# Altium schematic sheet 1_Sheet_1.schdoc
size 1005 x 452 mm; Name: A_A2; Symbol: A_A2; Device: A_A2; @Project Name: SpEIT_RHIZOTRON_TESTBOARD; REV: 1.0; Date: 2023-06-16; Sheet: 1/1; Draw By: ENOW MAGKEN; Company: UNIVERSITY OF MANCHESTER; Convert to PCB: yes; Add into BOM: yes
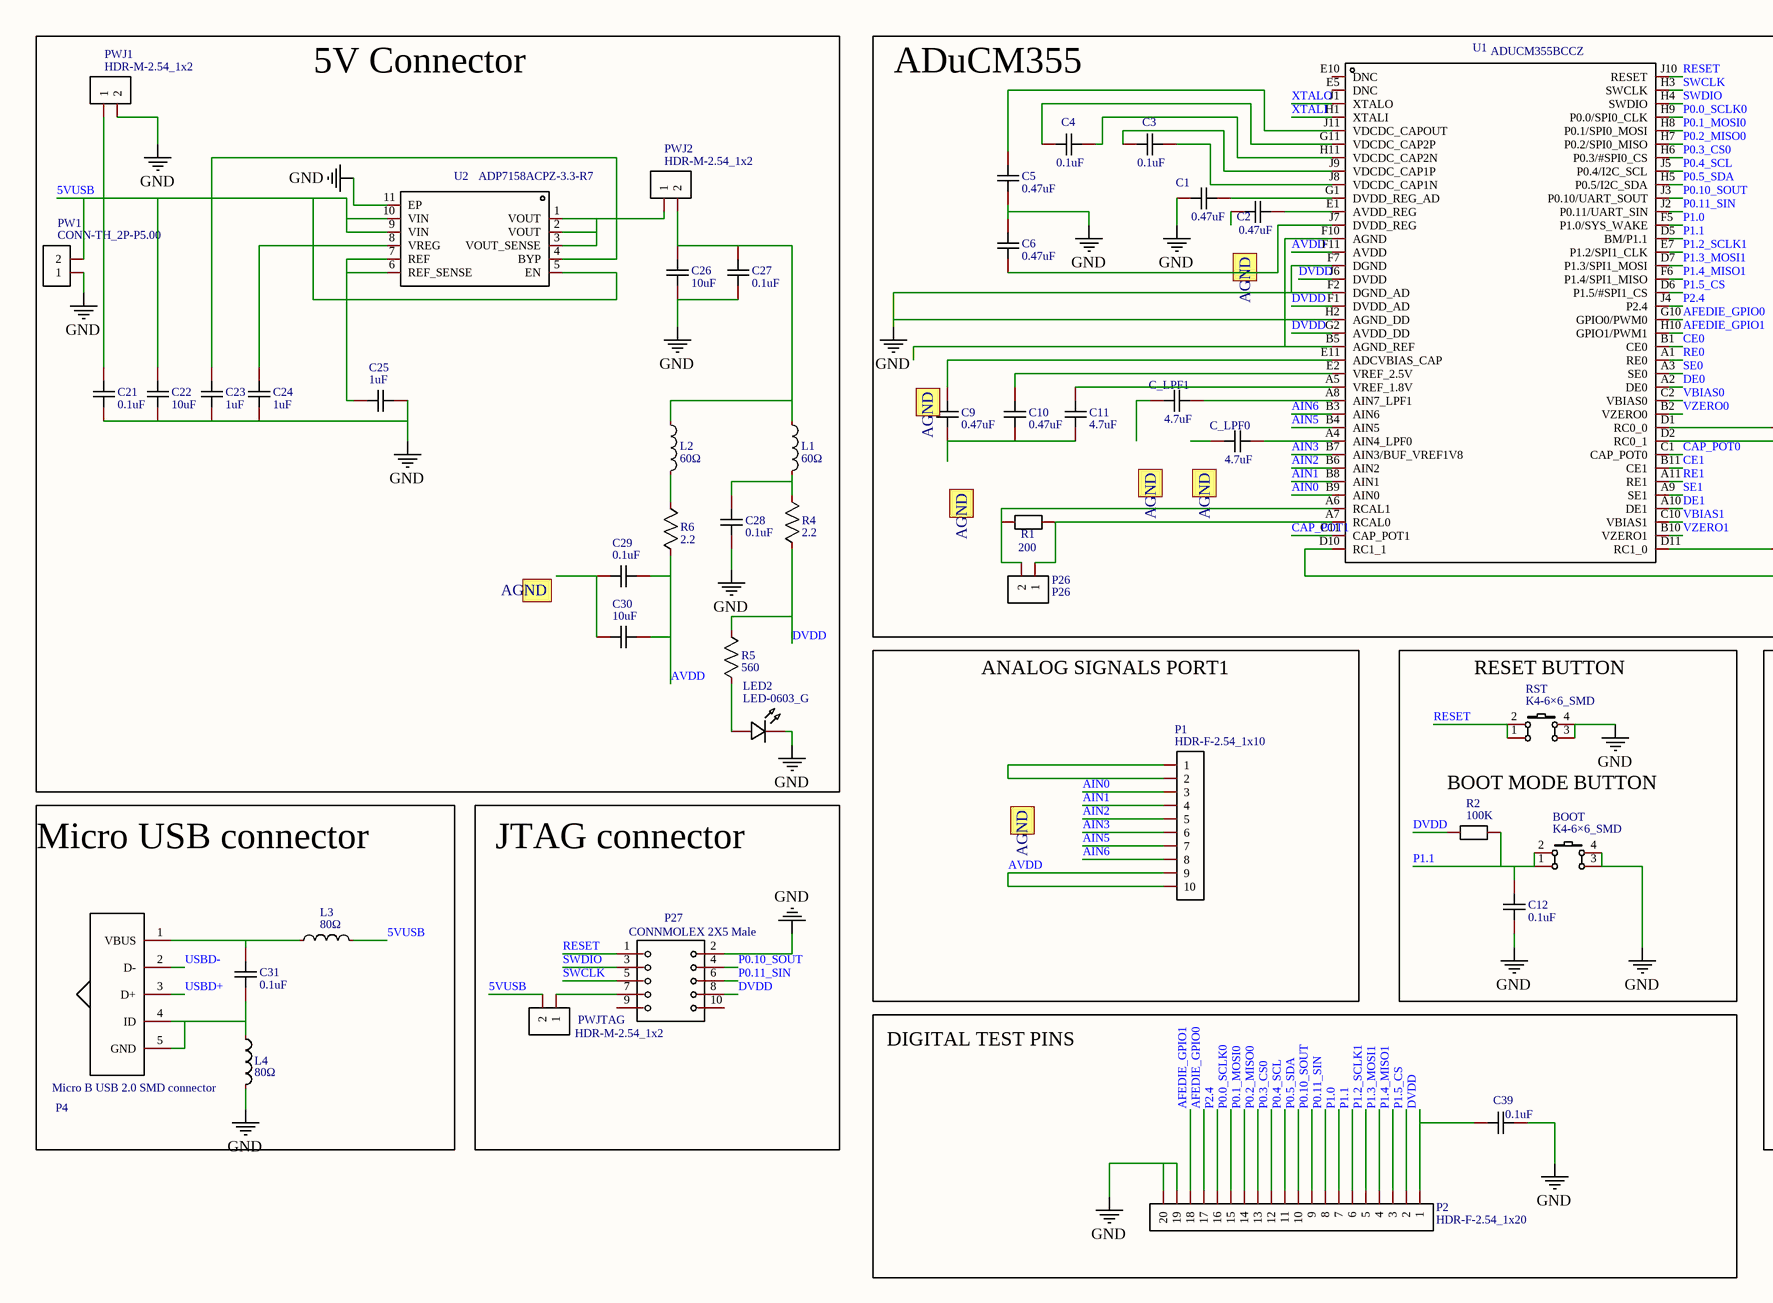
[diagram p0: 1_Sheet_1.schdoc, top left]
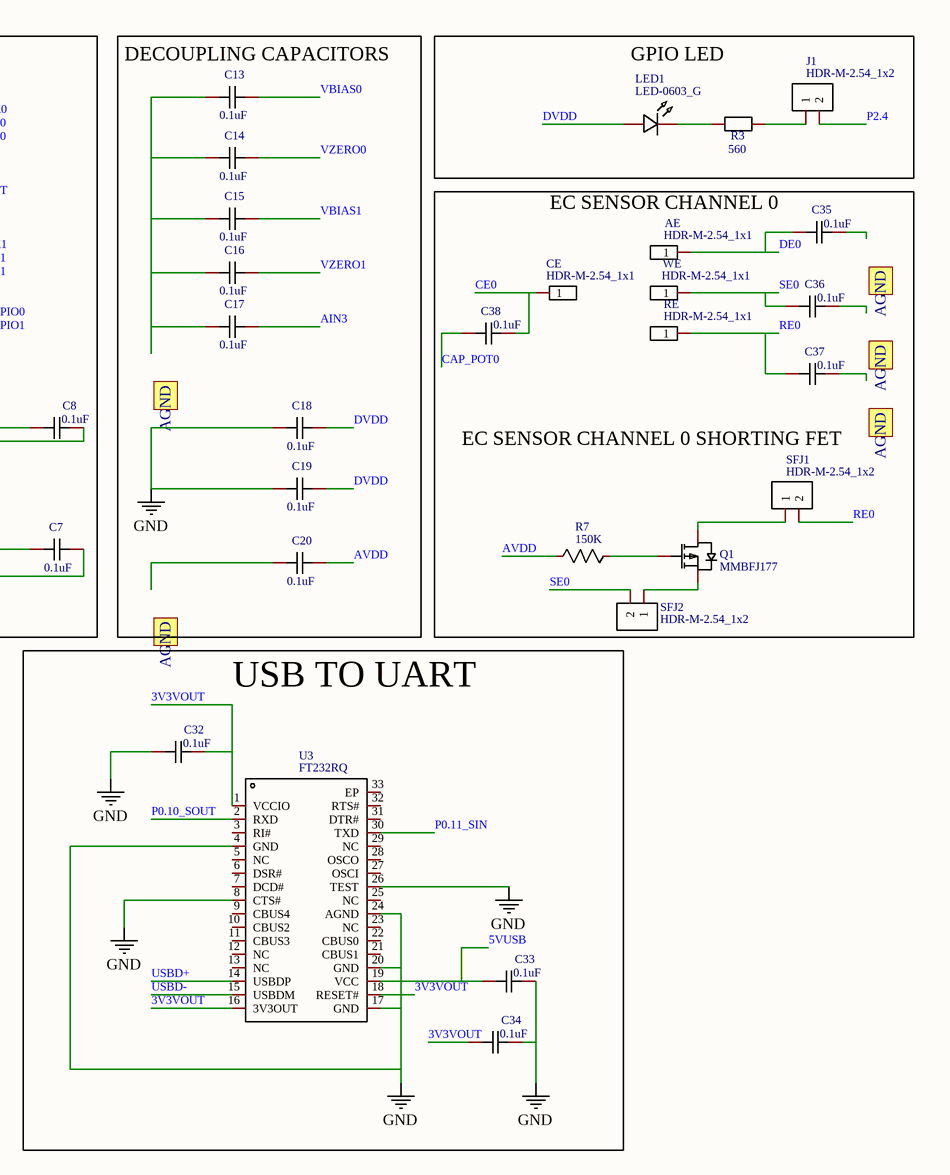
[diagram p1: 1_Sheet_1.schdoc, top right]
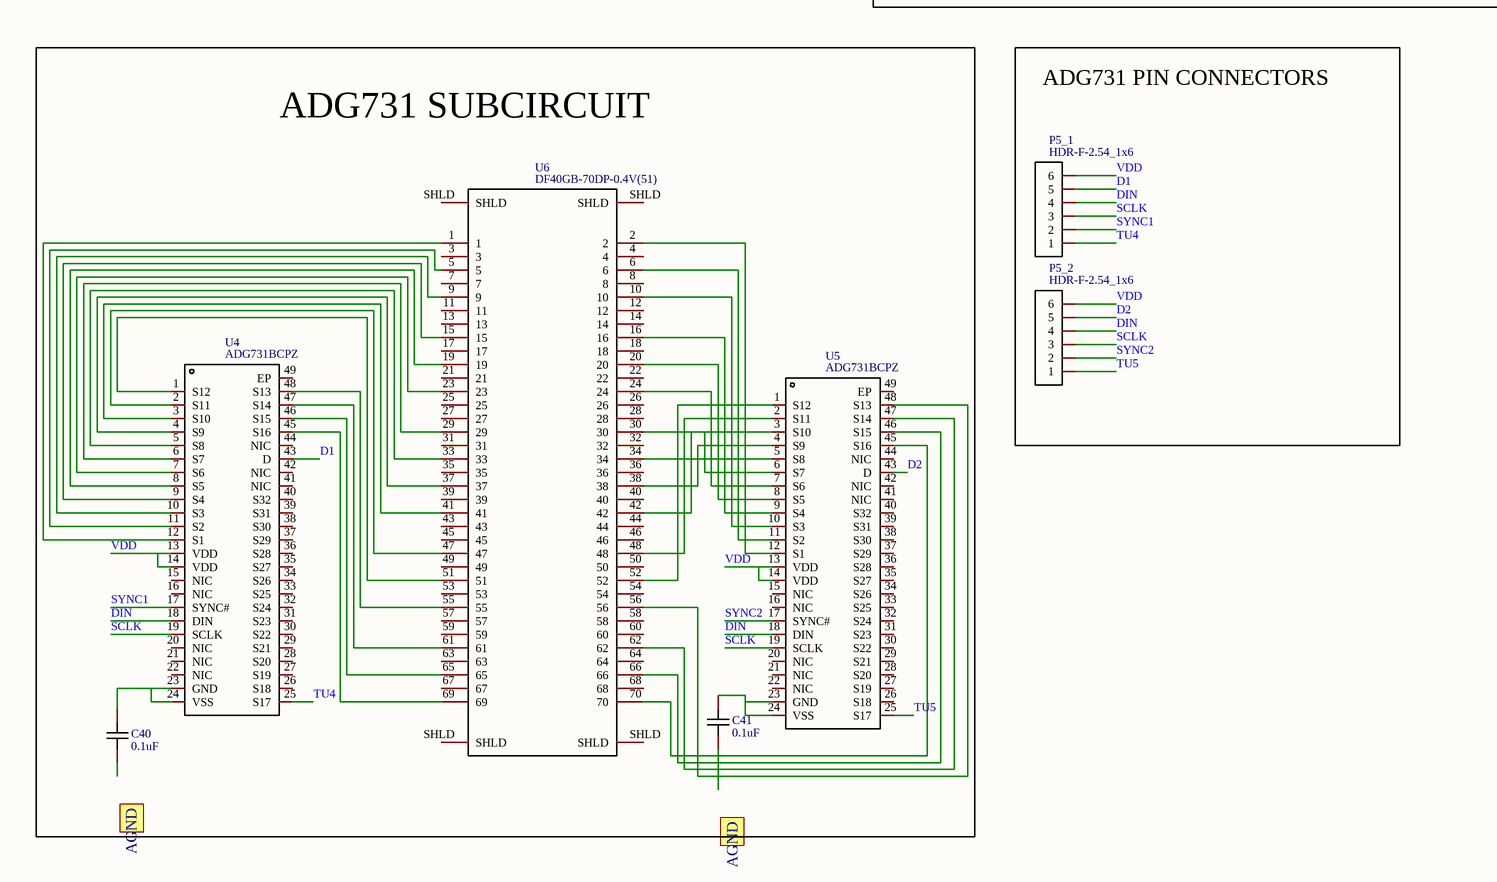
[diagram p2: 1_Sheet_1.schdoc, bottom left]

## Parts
AE  HDR-M-2.54_1x1  [HDR-M-2.54_1X1]
BOOT  K4-6×6_SMD  [KEY-SMD_4P-L6.0-W6.0-P3.90-LS10.0]
C1  0.47uF  [C0603]
C2  0.47uF  [C0603]
C3  0.1uF  [C0603]
C4  0.1uF  [C0603]
C5  0.47uF  [C0603]
C6  0.47uF  [C0603]
C7  0.1uF  [C0603]
C8  0.1uF  [C0603]
C9  0.47uF  [C0603]
C10  0.47uF  [C0603]
C11  4.7uF  [C0603]
C12  0.1uF  [C0603]
C13  0.1uF  [C0603]
C14  0.1uF  [C0603]
C15  0.1uF  [C0603]
C16  0.1uF  [C0603]
C17  0.1uF  [C0603]
C18  0.1uF  [C0603]
C19  0.1uF  [C0603]
C20  0.1uF  [C0603]
C21  0.1uF  [C0603]
C22  10uF  [C0603]
C23  1uF  [C0603]
C24  1uF  [C0603]
C25  1uF  [C0603]
C26  10uF  [C0603]
C27  0.1uF  [C0603]
C28  0.1uF  [C0603]
C29  0.1uF  [C0603]
C30  10uF  [C0603]
C31  0.1uF  [C0603]
C32  0.1uF  [C0603]
C33  0.1uF  [C0603]
C34  0.1uF  [C0603]
C35  0.1uF  [C0603]
C36  0.1uF  [C0603]
C37  0.1uF  [C0603]
C38  0.1uF  [C0603]
C39  0.1uF  [C0603]
C40  0.1uF  [C0603]
C41  0.1uF  [C0603]
C_LPF0  4.7uF  [C0603]
C_LPF1  4.7uF  [C0603]
CE  HDR-M-2.54_1x1  [HDR-M-2.54_1X1]
J1  HDR-M-2.54_1x2  [HDR-M-2.54_1X2]
L1  60Ω  [L0603]
L2  60Ω  [L0603]
L3  80Ω  [L1806]
L4  80Ω  [L1806]
LED1  LED-0603_G  [LED0603_GREEN]
LED2  LED-0603_G  [LED0603_GREEN]
P1  HDR-F-2.54_1x10  [HDR-F-2.54_1X10]
P2  HDR-F-2.54_1x20  [HDR-F-2.54_1X20]
P4  Micro B USB 2.0 SMD connector  [SD-47346-001]
P5_1  HDR-F-2.54_1x6  [HDR-F-2.54_1X6]
P5_2  HDR-F-2.54_1x6  [HDR-F-2.54_1X6]
P26  P26  [HDR-F-2.54_1X2]
P27  CONNMOLEX 2X5 Male  [JTAG-10PIN-2.54MM-PTH]
PW1  CONN-TH_2P-P5.00  [CONN-TH_2P-P5.00]
PWJ1  HDR-M-2.54_1x2  [HDR-M-2.54_1X2]
PWJ2  HDR-M-2.54_1x2  [HDR-M-2.54_1X2]
PWJTAG  HDR-M-2.54_1x2  [HDR-M-2.54_1X2]
Q1  MMBFJ177  [SOT-23-3_L3.0-W1.7-P0.95-LS2.9-BR]
R1  200  [R0603]
R2  100K  [R0603]
R3  560  [R0603]
R4  2.2  [R0603]
R5  560  [R0603]
R6  2.2  [R0603]
R7  150K  [R0603]
RE  HDR-M-2.54_1x1  [HDR-M-2.54_1X1]
RST  K4-6×6_SMD  [KEY-SMD_4P-L6.0-W6.0-P3.90-LS10.0]
SFJ1  HDR-M-2.54_1x2  [HDR-M-2.54_1X2]
SFJ2  HDR-M-2.54_1x2  [HDR-M-2.54_1X2]
U1  ADUCM355BCCZ  [LGA-72_L6.0-W5.0-TL_ADUCM355BCCZ-RL7]
U2  ADP7158ACPZ-3.3-R7  [LFCSP-10_L3.0-W3.0-P0.50-BL-EP]
U3  FT232RQ  [QFN-32_L5.0-W5.0-P0.50-BL-EP]
U4  ADG731BCPZ  [LFCSP-48_L7.0-W7.0-P0.50-TL-EP5.1]
U5  ADG731BCPZ  [LFCSP-48_L7.0-W7.0-P0.50-TL-EP5.1]
U6  DF40GB-70DP-0.4V(51)  [HIROSE DF40GB-70DP-0.4V(51)]
WE  HDR-M-2.54_1x1  [HDR-M-2.54_1X1]

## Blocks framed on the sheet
5V Connector: C21-C30 L1 L2 LED2 PW1 PWJ1 PWJ2 R4-R6 U2
ADuCM355: C1-C11 C_LPF0 C_LPF1 P26 R1 U1
DECOUPLING CAPACITORS: C13-C20
GPIO LED: J1 LED1 R3
ANALOG SIGNALS PORT1: P1
USB TO UART: C32-C34 U3
Micro USB connector: C31 L3 L4 P4
JTAG connector: P27 PWJTAG
DIGITAL TEST PINS: C39 P2
ADG731 SUBCIRCUIT: C40 C41 U4-U6
ADG731 PIN CONNECTORS: P5_1 P5_2

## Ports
AGND (out)

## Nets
GND: BOOT.3 BOOT.4 C1.1 C5.1 C6.2 C12.1 C18.1 C19.1 C21.1 C22.1 C23.1 C24.1 C25.1 C26.1 C27.1 C28.1 C32.1 C33.2 C34.2 C39.2 L4.2 LED2.2 P2.19 P2.20 P27.2 PW1.1 PWJ1.2 RST.3 RST.4 U1.F2(DGND_AD) U1.F7(DGND) U1.H2(AGND_DD) U2.11(EP) U3.4(GND) U3.8(CTS#) U3.17(GND) U3.20(GND) U3.24(AGND) U3.26(TEST)
3V3VOUT: C32.2 C34.1 U3.1(VCCIO) U3.16(3V3OUT) U3.18(RESET#)
5VUSB: C21.2 C22.2 C33.1 L3.2 PW1.2 PWJ1.1 PWJTAG.2 U2.5(EN) U2.9(VIN) U2.10(VIN) U3.19(VCC)
AFEDIE_GPIO0: P2.17 U1.G10(GPIO0/PWM0)
AFEDIE_GPIO1: P2.18 U1.H10(GPIO1/PWM1)
AIN0: P1.3 U1.B9(AIN0)
AIN1: P1.4 U1.B8(AIN1)
AIN2: P1.5 U1.B6(AIN2)
AIN3: C17.2 P1.6 U1.B7(AIN3/BUF_VREF1V8)
AIN5: P1.7 U1.B4(AIN5)
AIN6: P1.8 U1.B3(AIN6)
AVDD: C20.2 C29.1 C30.1 P1.9 P1.10 R6.1 R7.2 U1.F11(AVDD)
CAP_POT0: C38.1 U1.C1(CAP_POT0)
CAP_POT1: U1.C11(CAP_POT1)
CE0: C38.2 CE.1 U1.B1(CE0)
CE1: U1.B11(CE1)
D1: P5_1.5 U4.43(D)
D2: P5_2.5 U5.43(D)
DE0: AE.1 C35.1 U1.A2(DE0)
DE1: U1.A10(DE1)
DIN: P5_1.4 P5_2.4 U4.18(DIN) U5.18(DIN)
DVDD: C18.2 C19.2 C39.1 LED1.1 P2.1 P27.8 R2.2 R4.1 R5.2 U1.F1(DVDD_AD) U1.G2(AVDD_DD) U1.J6(DVDD)
P0.0_SCLK0: P2.15 U1.H9(P0.0/SPI0_CLK)
P0.1_MOSI0: P2.14 U1.H8(P0.1/SPI0_MOSI)
P0.2_MISO0: P2.13 U1.H7(P0.2/SPI0_MISO)
P0.3_CS0: P2.12 U1.H6(P0.3/#SPI0_CS)
P0.4_SCL: P2.11 U1.J5(P0.4/I2C_SCL)
P0.5_SDA: P2.10 U1.H5(P0.5/I2C_SDA)
P0.10_SOUT: P2.9 P27.4 U1.J3(P0.10/UART_SOUT) U3.2(RXD)
P0.11_SIN: P2.8 P27.6 U1.J2(P0.11/UART_SIN) U3.30(TXD)
P1.0: P2.7 U1.F5(P1.0/SYS_WAKE)
P1.1: BOOT.1 BOOT.2 C12.2 P2.6 R2.1 U1.D5(BM/P1.1)
P1.2_SCLK1: P2.5 U1.E7(P1.2/SPI1_CLK)
P1.3_MOSI1: P2.4 U1.D7(P1.3/SPI1_MOSI)
P1.4_MISO1: P2.3 U1.F6(P1.4/SPI1_MISO)
P1.5_CS: P2.2 U1.D6(P1.5/#SPI1_CS)
P2.4: J1.2 P2.16 U1.J4(P2.4)
RE0: C37.1 RE.1 SFJ1.2 U1.A1(RE0)
RE1: U1.A11(RE1)
RESET: P27.1 RST.1 RST.2 U1.J10(RESET)
SCLK: P5_1.3 P5_2.3 U4.19(SCLK) U5.19(SCLK)
SE0: C36.1 SFJ2.2 U1.A3(SE0) WE.1
SE1: U1.A9(SE1)
SWCLK: P27.5 U1.H3(SWCLK)
SWDIO: P27.3 U1.H4(SWDIO)
SYNC1: P5_1.2 U4.17(SYNC#)
SYNC2: P5_2.2 U5.17(SYNC#)
TU4: P5_1.1 U4.25(S17)
TU5: P5_2.1 U5.25(S17)
USBD+: P4.3(D+) U3.14(USBDP)
USBD-: P4.2(D-) U3.15(USBDM)
VBIAS0: C13.2 U1.C2(VBIAS0)
VBIAS1: C15.2 U1.C10(VBIAS1)
VDD: P5_1.6 P5_2.6 U4.13(VDD) U4.14(VDD) U5.13(VDD) U5.14(VDD)
VZERO0: C14.2 U1.B2(VZERO0)
VZERO1: C16.2 U1.B10(VZERO1)
XTALI: U1.H1(XTALI)
XTALO: U1.J1(XTALO)
NetC1_2: C1.2 U1.G1(DVDD_REG_AD)
NetC2_1: C2.1 U1.E1(AVDD_REG)
NetC3_1: C3.1 U1.J9(VDCDC_CAP1P)
NetC3_2: C3.2 U1.J8(VDCDC_CAP1N)
NetC4_1: C4.1 U1.G11(VDCDC_CAP2P)
NetC4_2: C4.2 U1.H11(VDCDC_CAP2N)
NetC5_2: C5.2 U1.J11(VDCDC_CAPOUT)
NetC6_1: C6.1 U1.J7(DVDD_REG)
NetC7_1: C7.1 U1.D11(RC1_0)
NetC7_2: C7.2 U1.D10(RC1_1)
NetC8_1: C8.1 U1.D1(RC0_0)
NetC8_2: C8.2 U1.D2(RC0_1)
NetC9_1: C9.1 C10.1 C11.1
NetC9_2: C9.2 U1.E11(ADCVBIAS_CAP)
NetC10_2: C10.2 U1.E2(VREF_2.5V)
NetC11_2: C11.2 U1.A5(VREF_1.8V)
NetC13_1: C13.1 C14.1 C15.1 C16.1 C17.1
NetC23_2: C23.2 U2.4(BYP)
NetC24_2: C24.2 U2.8(VREG)
NetC25_2: C25.2 U2.6(REF_SENSE) U2.7(REF)
NetC26_2: C26.2 C27.2 L1.1 L2.1 PWJ2.2
NetC28_2: C28.2 L1.2 R4.2
NetC29_2: C29.2 C30.2
NetC31_1: C31.1 L4.1 P4.4(ID) P4.5(GND)
NetC31_2: C31.2 L3.1 P4.1(VBUS)
NetC40_1: C40.1 U4.23(GND) U4.24(VSS)
NetC41_1: C41.1 U5.23(GND) U5.24(VSS)
NetC_LPF0_2: C_LPF0.2 U1.A4(AIN4_LPF0)
NetC_LPF1_2: C_LPF1.2 U1.A8(AIN7_LPF1)
NetJ1_1: J1.1 R3.2
NetL2_2: L2.2 R6.2
NetLED1_2: LED1.2 R3.1
NetLED2_1: LED2.1 R5.1
NetP1_1: P1.1 P1.2
NetP26_1: P26.1 R1.2 U1.A7(RCAL0)
NetP26_2: P26.2 R1.1 U1.A6(RCAL1)
NetP27_7: P27.7 PWJTAG.1
NetPWJ2_1: PWJ2.1 U2.1(VOUT) U2.2(VOUT) U2.3(VOUT_SENSE)
NetQ1_1: Q1.1(D) SFJ1.1
NetQ1_2: Q1.2(S) SFJ2.1
NetQ1_3: Q1.3(G) R7.1
NetU1_B5: U1.B5(AGND_REF) U1.F10(AGND)
NetU4_1: U4.1(S12) U6.51
NetU4_2: U4.2(S11) U6.47
NetU4_3: U4.3(S10) U6.41
NetU4_4: U4.4(S9) U6.37
NetU4_5: U4.5(S8) U6.33
NetU4_6: U4.6(S7) U6.29
NetU4_7: U4.7(S6) U6.23
NetU4_8: U4.8(S5) U6.19
NetU4_9: U4.9(S4) U6.15
NetU4_10: U4.10(S3) U6.9
NetU4_11: U4.11(S2) U6.5
NetU4_12: U4.12(S1) U6.1
NetU4_45: U4.45(S16) U6.69
NetU4_46: U4.46(S15) U6.65
NetU4_47: U4.47(S14) U6.61
NetU4_48: U4.48(S13) U6.55
NetU5_1: U5.1(S12) U6.52
NetU5_2: U5.2(S11) U6.48
NetU5_3: U5.3(S10) U5.6(S7) U6.30 U6.42
NetU5_4: U5.4(S9) U6.38
NetU5_5: U5.5(S8) U6.34
NetU5_7: U5.7(S6) U6.24
NetU5_8: U5.8(S5) U6.20
NetU5_9: U5.9(S4) U6.16
NetU5_10: U5.10(S3) U6.10
NetU5_11: U5.11(S2) U6.6
NetU5_12: U5.12(S1) U6.2
NetU5_45: U5.45(S16) U6.70
NetU5_46: U5.46(S15) U6.66
NetU5_47: U5.47(S14) U6.62
NetU5_48: U5.48(S13) U6.56

Not connected (* = marked no-connect by the designer): C2 2; C20 1; C35 2; C36 2; C37 2; C40 2; C41 2; C_LPF0 1; C_LPF1 1; P27 9 10; U1 E5(DNC) E10(DNC); U3 3(RI#) 5(NC) 6(DSR#) 7(DCD#) 9(CBUS4) 10(CBUS2) 11(CBUS3) 12(NC) 13(NC) 21(CBUS1) 22(CBUS0) 23(NC) 25(NC) 27(OSCI) 28(OSCO) 29(NC) 31(DTR#) 32(RTS#) 33(EP); U4 15(NIC) 16(NIC) 20(NIC) 21(NIC) 22(NIC) 26(S18) 27(S19) 28(S20) 29(S21) 30(S22) 31(S23) 32(S24) 33(S25) 34(S26) 35(S27) 36(S28) 37(S29) 38(S30) 39(S31) 40(S32) 41(NIC) 42(NIC) 44(NIC) 49(EP); U5 15(NIC) 16(NIC) 20(NIC) 21(NIC) 22(NIC) 26(S18) 27(S19) 28(S20) 29(S21) 30(S22) 31(S23) 32(S24) 33(S25) 34(S26) 35(S27) 36(S28) 37(S29) 38(S30) 39(S31) 40(S32) 41(NIC) 42(NIC) 44(NIC) 49(EP); U6 3 4 7 8 11 12 13 14 17 18 21 22 25 26 27 28 31 32 35 36 39 40 43 44 45 46 49 50 53 54 57 58 59 60 63 64 67 68 SHLD

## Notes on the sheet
- (near AE) EC SENSOR CHANNEL 0
- EC SENSOR CHANNEL 0 SHORTING FET
- (near RST) RESET BUTTON
- BOOT MODE BUTTON

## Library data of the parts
AE CE RE WE = HDR-M-2.54_1x1: Convert to PCB: yes
BOOT RST = K4-6×6_SMD: Manufacturer: 韩国韩荣; Manufacturer Part: K2-6639SP-D4SC-04; Convert to PCB: yes
C1 C2 C5 C6 C9 C10 = 0.47uF: Convert to PCB: yes
C3 C4 C7 C8 C12-C21 C27-C29 C31-C41 = 0.1uF: Convert to PCB: yes
C11 C_LPF0 C_LPF1 = 4.7uF: Convert to PCB: yes
C22 C26 C30 = 10uF: Convert to PCB: yes
C23-C25 = 1uF: Convert to PCB: yes
J1 PWJ1 PWJ2 PWJTAG SFJ1 SFJ2 = HDR-M-2.54_1x2: Convert to PCB: yes
L1 L2 = 60Ω: Manufacturer: muRata(村田); Manufacturer Part: BLM18PG600SH1D; Convert to PCB: yes
L3 L4 = 80Ω: Manufacturer: muRata(村田); Manufacturer Part: BLM41PF800SN1L; Convert to PCB: yes
LED1 LED2 = LED-0603_G: Manufacturer: EVERLIGHT(台湾亿光); Manufacturer Part: 19-217/GHC-YR1S2/3T; Convert to PCB: yes
P1 = HDR-F-2.54_1x10: Convert to PCB: yes
P2 = HDR-F-2.54_1x20: Convert to PCB: yes
P4 = Micro B USB 2.0 SMD connector: Manufacturer: Molex; Manufacturer Part: 0473460001; Convert to PCB: yes
P5_1 P5_2 = HDR-F-2.54_1x6: Convert to PCB: yes
P26 = P26: Convert to PCB: yes
P27 = CONNMOLEX 2X5 Male: MolexConnectore2X52.54; Convert to PCB: yes
PW1 = CONN-TH_2P-P5.00: Convert to PCB: yes
Q1 = MMBFJ177: Manufacturer: onsemi(安森美); Convert to PCB: yes
R1 = 200: Convert to PCB: yes
R2 = 100K: Convert to PCB: yes
R3 R5 = 560: Convert to PCB: yes
R4 R6 = 2.2: Convert to PCB: yes
R7 = 150K: Convert to PCB: yes
U1 = ADUCM355BCCZ: Manufacturer: ADI(亚德诺)/LINEAR(凌特); Convert to PCB: yes
U2 = ADP7158ACPZ-3.3-R7: Manufacturer: ADI(亚德诺)/LINEAR; Convert to PCB: yes
U3 = FT232RQ: Manufacturer: FTDI(飞特帝亚); Manufacturer Part: FT232RQ-REEL; Convert to PCB: yes
U4 U5 = ADG731BCPZ: Manufacturer: ADI(亚德诺)/LINEAR; Convert to PCB: yes
U6 = DF40GB-70DP-0.4V(51): Manufacturer Part: Hirose; Convert to PCB: yes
